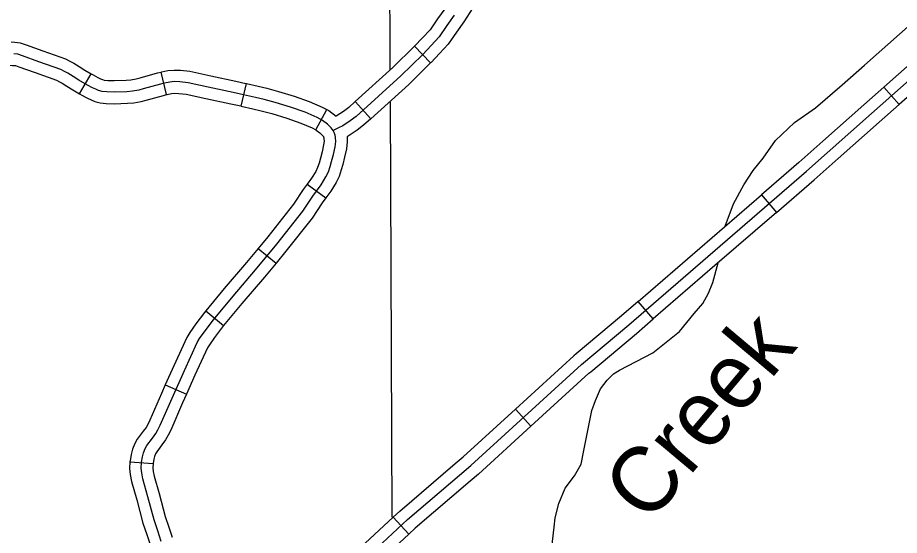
# Model space of a CAD drawing. Extents: x -3711 to 825, y -151 to 1050.
# Drawn here: x -2743.1 to -2679, y 150.8 to 188.4 of the extents above; entities that cross this region are included whole.
import ezdxf

# ---------------------------------------------------------------- set-up
doc = ezdxf.new("R2010")
doc.units = 0
for name, color, linetype in [('Level 31', 7, 'Continuous'), ('Level 32', 7, 'Continuous'), ('Level 35', 7, 'Continuous'), ('Level 5', 7, 'Continuous')]:
    doc.layers.add(name, color=color, linetype=linetype)

msp = doc.modelspace()

# ---------------------------------------------------------------- linework, layer by layer
at = {"layer": 'Level 31'}
for p, q in [((-2679.059, 182.078), (-2680.167, 183.343)), ((-2679.059, 182.078), (-2679.059, 182.078)), ((-2689.05, 175.531), (-2687.951, 174.258)), ((-2696.906, 166.52), (-2698.006, 167.793)), ((-2706.921, 159.978), (-2705.789, 158.735)), ((-2714.651, 150.909), (-2715.799, 152.137)), ((-2714.651, 150.909), (-2714.651, 150.909))]:
    msp.add_line(p, q, dxfattribs=at)
for points in [[(-2680.167, 183.343), (-2678.024, 185.219), (-2676.156, 186.939), (-2675.775, 187.286)], [(-2674.644, 186.042), (-2675.021, 185.699), (-2676.901, 183.968), (-2679.059, 182.078)], [(-2716.925, 149.935), (-2714.765, 151.953), (-2710.153, 155.893), (-2702.131, 163.209), (-2698.682, 166.097), (-2685.785, 177.24), (-2681.062, 181.442), (-2677.463, 184.593)], [(-2680.166, 183.343), (-2681.618, 182.072), (-2684.603, 179.417)], [(-2683.486, 178.161), (-2680.505, 180.812), (-2679.059, 182.078)], [(-2684.603, 179.417), (-2686.339, 177.872), (-2689.05, 175.531)], [(-2687.951, 174.258), (-2685.231, 176.608), (-2683.486, 178.161)], [(-2693.528, 171.662), (-2689.05, 175.531)], [(-2687.951, 174.258), (-2692.428, 170.389)], [(-2698.006, 167.793), (-2693.528, 171.662)], [(-2692.428, 170.389), (-2696.906, 166.52)], [(-2698.006, 167.793), (-2699.226, 166.738), (-2702.516, 163.982)], [(-2701.437, 162.693), (-2698.137, 165.457), (-2696.906, 166.52)], [(-2702.516, 163.982), (-2702.684, 163.842), (-2706.921, 159.978)], [(-2705.789, 158.735), (-2701.577, 162.576), (-2701.437, 162.693)], [(-2711.29, 156.027), (-2710.71, 156.523), (-2706.921, 159.978)], [(-2705.789, 158.735), (-2709.597, 155.262), (-2710.198, 154.749)], [(-2715.799, 152.137), (-2715.325, 152.58), (-2711.291, 156.027)], [(-2710.198, 154.749), (-2714.204, 151.326), (-2714.651, 150.909)], [(-2715.799, 152.137), (-2717.496, 150.552), (-2718.818, 149.337), (-2719.938, 148.325), (-2720.161, 148.107)], [(-2718.983, 146.907), (-2718.785, 147.101), (-2717.686, 148.094), (-2716.354, 149.318), (-2714.651, 150.909)]]:
    msp.add_lwpolyline(points, dxfattribs=at)
at = {"layer": 'Level 32'}
for p, q in [((-2714.252, 186.307), (-2713.076, 185.106)), ((-2732.248, 182.807), (-2732.638, 184.443)), ((-2738.578, 182.862), (-2737.736, 184.317)), ((-2726.825, 181.968), (-2726.443, 183.605)), ((-2718.555, 182.293), (-2717.426, 181.047)), ((-2721.414, 180.241), (-2720.617, 181.721)), ((-2722.037, 176.297), (-2720.681, 175.304)), ((-2725.606, 171.639), (-2724.306, 170.573)), ((-2729.405, 167.111), (-2728.115, 166.033)), ((-2732.344, 161.74), (-2730.808, 161.058)), ((-2734.912, 156.139), (-2733.234, 156.031))]:
    msp.add_line(p, q, dxfattribs=at)
for points in [[(-2710.877, 190.894), (-2711.642, 189.658), (-2712.052, 189.035), (-2712.578, 188.305), (-2713.109, 187.515), (-2713.658, 186.935), (-2714.244, 186.315), (-2714.252, 186.307)], [(-2709.447, 190.01), (-2710.225, 188.754), (-2710.667, 188.081), (-2711.198, 187.344), (-2711.792, 186.461), (-2712.436, 185.78), (-2713.044, 185.137), (-2713.076, 185.106)], [(-2711.36, 188.558), (-2711.888, 187.824), (-2712.451, 186.988), (-2713.047, 186.357), (-2713.644, 185.726), (-2715.246, 184.157), (-2718.485, 181.222), (-2718.911, 180.898), (-2719.459, 180.533), (-2719.757, 180.383), (-2720.153, 180.202)], [(-2743.535, 186.622), (-2743.272, 186.601), (-2742.895, 186.556), (-2742.446, 186.422), (-2741.234, 185.98), (-2739.606, 185.396), (-2739.275, 185.238), (-2738.99, 185.082), (-2738.595, 184.836), (-2738.186, 184.577), (-2737.736, 184.317)], [(-2737.991, 183.494), (-2738.622, 183.858), (-2739.042, 184.124), (-2739.414, 184.356), (-2739.658, 184.489), (-2739.93, 184.619), (-2741.52, 185.189), (-2742.71, 185.624), (-2743.066, 185.73), (-2743.354, 185.764)], [(-2714.252, 186.307), (-2715.823, 184.769), (-2718.555, 182.293)], [(-2713.076, 185.106), (-2714.67, 183.545), (-2717.426, 181.047)], [(-2743.669, 184.946), (-2743.437, 184.927), (-2743.236, 184.904), (-2742.975, 184.826), (-2741.806, 184.399), (-2740.254, 183.842), (-2740.04, 183.74), (-2739.837, 183.629), (-2739.488, 183.412), (-2739.057, 183.139), (-2738.578, 182.862)], [(-2737.736, 184.317), (-2737.582, 184.228), (-2737.25, 184.049), (-2737.049, 183.956), (-2736.917, 183.899), (-2736.785, 183.863), (-2736.527, 183.838), (-2736.054, 183.818), (-2735.198, 183.855), (-2734.84, 183.886), (-2734.455, 183.948), (-2734.166, 184.025), (-2732.91, 184.378), (-2732.638, 184.443)], [(-2732.638, 184.442), (-2732.593, 184.453), (-2732.153, 184.551), (-2731.71, 184.588), (-2731.235, 184.571), (-2730.561, 184.493), (-2729.051, 184.176), (-2727.224, 183.782), (-2726.487, 183.615), (-2726.443, 183.605)], [(-2732.642, 150.379), (-2732.895, 151.136), (-2733.161, 151.934), (-2733.609, 153.616), (-2733.987, 154.919), (-2734.057, 155.34), (-2734.099, 155.69), (-2734.071, 156.125), (-2734.001, 156.517), (-2733.931, 156.797), (-2733.805, 157.106), (-2733.679, 157.33), (-2733.273, 157.876), (-2733.035, 158.199), (-2732.881, 158.479), (-2732.712, 158.815), (-2731.858, 160.763), (-2730.962, 162.781), (-2730.024, 164.799), (-2729.856, 165.094), (-2729.45, 165.668), (-2728.848, 166.467), (-2727.42, 168.177), (-2725.795, 170.082), (-2724.255, 171.96), (-2722.365, 174.343), (-2721.637, 175.422), (-2721.02, 176.263), (-2720.684, 176.823), (-2720.502, 177.188), (-2720.376, 177.58), (-2720.264, 177.958), (-2720.138, 178.449), (-2720.014, 179.014), (-2719.97, 179.402), (-2719.984, 179.682), (-2720.012, 179.864), (-2720.082, 180.06), (-2720.153, 180.202), (-2720.306, 180.398), (-2720.569, 180.662), (-2720.93, 180.935), (-2721.31, 181.139), (-2722.197, 181.518), (-2723.261, 181.882), (-2724.367, 182.233), (-2725.176, 182.445), (-2725.799, 182.591), (-2726.676, 182.796), (-2727.406, 182.961), (-2729.226, 183.354), (-2730.696, 183.662), (-2731.298, 183.732), (-2731.69, 183.746), (-2732.026, 183.718), (-2732.404, 183.634), (-2732.698, 183.564), (-2733.945, 183.214), (-2734.279, 183.125), (-2734.737, 183.051), (-2735.144, 183.016), (-2736.054, 182.976), (-2736.586, 182.999), (-2736.935, 183.034), (-2737.193, 183.102), (-2737.393, 183.188), (-2737.627, 183.298), (-2737.991, 183.494)], [(-2726.443, 183.605), (-2725.607, 183.41), (-2724.973, 183.261), (-2724.133, 183.04), (-2722.998, 182.681), (-2721.895, 182.303), (-2720.944, 181.897), (-2720.617, 181.721)], [(-2738.578, 182.862), (-2738.401, 182.76), (-2738.005, 182.546), (-2737.737, 182.421), (-2737.468, 182.306), (-2737.086, 182.204), (-2736.645, 182.16), (-2736.053, 182.135), (-2735.09, 182.177), (-2734.634, 182.216), (-2734.104, 182.302), (-2733.724, 182.402), (-2732.487, 182.75), (-2732.248, 182.807)], [(-2732.248, 182.807), (-2732.216, 182.815), (-2731.9, 182.885), (-2731.67, 182.904), (-2731.362, 182.893), (-2730.831, 182.831), (-2729.401, 182.531), (-2727.587, 182.14), (-2726.864, 181.977), (-2726.825, 181.968)], [(-2726.825, 181.968), (-2725.991, 181.773), (-2725.379, 181.629), (-2724.601, 181.425), (-2723.524, 181.084), (-2722.498, 180.733), (-2721.675, 180.381), (-2721.414, 180.241)], [(-2718.555, 182.293), (-2719.023, 181.87), (-2719.4, 181.583), (-2719.928, 181.23)], [(-2720.617, 181.721), (-2720.474, 181.644), (-2719.928, 181.23)], [(-2717.426, 181.047), (-2717.948, 180.575), (-2718.423, 180.213), (-2719.145, 179.731)], [(-2721.414, 180.241), (-2721.386, 180.225), (-2721.123, 180.026), (-2720.937, 179.841), (-2720.867, 179.751), (-2720.857, 179.73), (-2720.831, 179.657), (-2720.822, 179.597), (-2720.813, 179.428), (-2720.845, 179.152), (-2720.956, 178.643), (-2721.075, 178.182), (-2721.18, 177.828), (-2721.283, 177.506), (-2721.422, 177.228), (-2721.721, 176.728), (-2722.037, 176.297)], [(-2719.145, 179.731), (-2719.127, 179.375), (-2719.184, 178.877), (-2719.32, 178.254), (-2719.454, 177.734), (-2719.573, 177.332), (-2719.722, 176.869), (-2719.947, 176.419), (-2720.319, 175.797), (-2720.681, 175.304)], [(-2722.037, 176.297), (-2722.324, 175.905), (-2723.043, 174.84), (-2724.909, 172.488), (-2725.606, 171.639)], [(-2720.681, 175.304), (-2720.949, 174.938), (-2721.686, 173.846), (-2723.601, 171.433), (-2724.306, 170.573)], [(-2725.606, 171.639), (-2726.44, 170.622), (-2728.062, 168.719), (-2729.405, 167.111)], [(-2724.306, 170.573), (-2725.15, 169.543), (-2726.777, 167.634), (-2728.115, 166.033)], [(-2729.405, 167.111), (-2729.506, 166.99), (-2730.129, 166.164), (-2730.566, 165.546), (-2730.771, 165.186), (-2731.727, 163.129), (-2732.344, 161.74)], [(-2728.115, 166.033), (-2728.189, 165.944), (-2728.771, 165.172), (-2729.146, 164.641), (-2729.277, 164.413), (-2730.197, 162.433), (-2730.808, 161.058)], [(-2732.344, 161.74), (-2732.627, 161.103), (-2733.474, 159.172), (-2733.625, 158.869), (-2733.744, 158.653), (-2733.948, 158.377), (-2734.385, 157.788), (-2734.563, 157.472), (-2734.732, 157.06), (-2734.823, 156.693), (-2734.907, 156.226), (-2734.912, 156.139)], [(-2730.808, 161.058), (-2731.089, 160.424), (-2731.951, 158.458), (-2732.136, 158.089), (-2732.325, 157.745), (-2732.597, 157.376), (-2732.972, 156.871), (-2733.046, 156.739), (-2733.13, 156.535), (-2733.178, 156.341), (-2733.235, 156.023), (-2733.234, 156.031)], [(-2734.912, 156.139), (-2734.943, 155.667), (-2734.889, 155.221), (-2734.808, 154.733), (-2734.419, 153.391), (-2733.966, 151.693), (-2733.692, 150.87), (-2733.426, 150.073), (-2733.406, 150.028)], [(-2733.234, 156.031), (-2733.255, 155.713), (-2733.224, 155.459), (-2733.166, 155.106), (-2732.799, 153.841), (-2732.355, 152.176), (-2732.097, 151.401), (-2731.858, 150.685), (-2731.873, 150.718)]]:
    msp.add_lwpolyline(points, dxfattribs=at)
at = {"layer": 'Level 35'}
for points in [[(-2691.675, 173.262), (-2691.077, 174.885), (-2690.341, 176.254), (-2689.658, 177.306), (-2688.922, 178.2), (-2688.028, 179.463), (-2686.661, 180.779), (-2685.136, 181.831), (-2683.191, 183.515), (-2681.561, 184.936), (-2675.41, 190.408), (-2671.625, 193.092), (-2668.47, 195.67), (-2666.42, 197.196), (-2664.843, 198.143), (-2663.213, 199.406), (-2662.004, 200.3)], [(-2703.767, 153.135), (-2703.307, 154.233), (-2702.623, 155.128), (-2702.15, 155.97), (-2701.94, 156.97), (-2701.361, 159.864), (-2701.099, 160.6), (-2700.731, 161.442), (-2700.257, 162.074), (-2699.784, 162.547), (-2699.364, 162.81), (-2696.945, 164.073), (-2695, 165.599), (-2693.948, 166.915), (-2693.318, 167.651), (-2692.897, 168.388), (-2692.582, 169.177), (-2692.197, 170.59)], [(-2704.109, 151.398), (-2704.039, 152.085), (-2703.767, 153.135)], [(-2707.623, 145.349), (-2706.93, 145.974), (-2706.16, 146.626), (-2705.371, 147.204), (-2704.898, 147.678), (-2704.583, 148.151), (-2704.372, 148.888), (-2704.215, 150.361), (-2704.109, 151.398)]]:
    msp.add_lwpolyline(points, dxfattribs=at)
at = {"layer": 'Level 5'}
for points in [[(-2716.171, 255.034), (-2716.099, 200.894), (-2716.028, 184.599)], [(-2716.018, 182.262), (-2715.887, 152.128)]]:
    msp.add_lwpolyline(points, dxfattribs=at)

# ---------------------------------------------------------------- texts
at = {"layer": 'Level 35'}
msp.add_text('Creek', height=4.7343, rotation=49.97457, dxfattribs=at).set_placement((-2697.238, 151.543))

doc.saveas('drawing.dxf')
